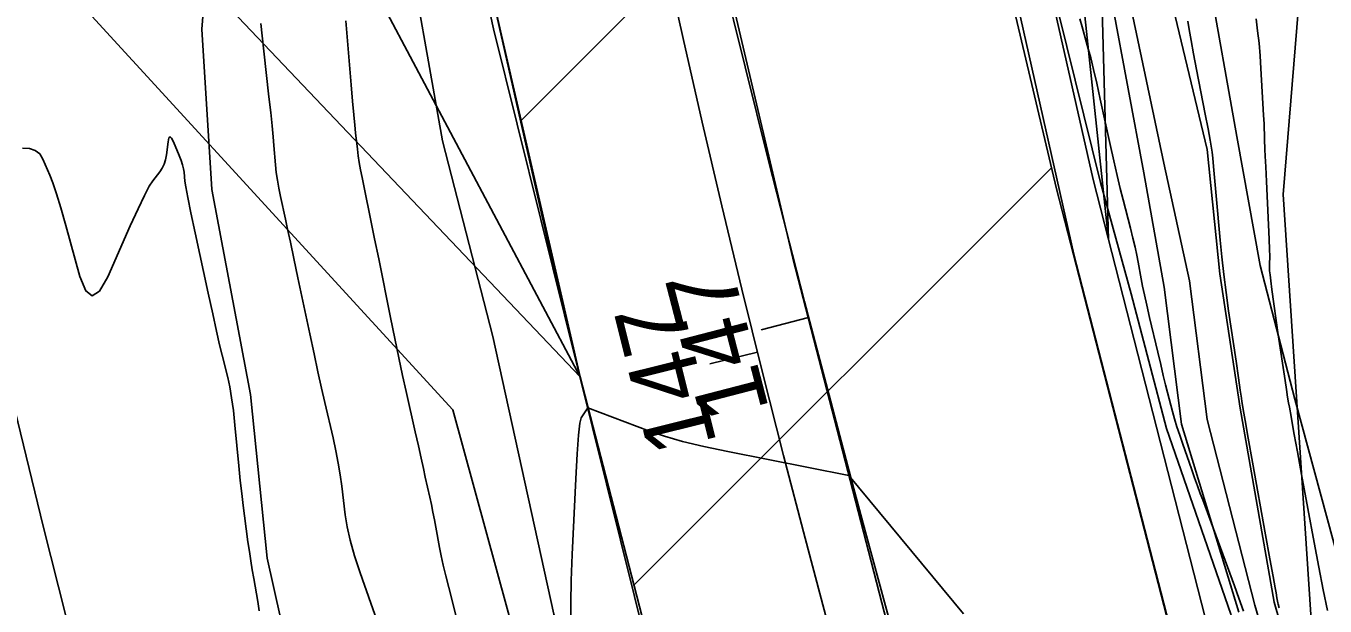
# Model space of a CAD drawing. Extents: x 2030588 to 2035216, y 462285 to 465007.
# Drawn here: x 2031244.3 to 2031297.3, y 464172.9 to 464196.5 of the extents above; entities that cross this region are included whole.
import ezdxf

# ---------------------------------------------------------------- set-up
doc = ezdxf.new("R2010")
doc.units = 0
for name, color, linetype in [('DR_X_Ditch', 7, 'Continuous'), ('DT_P_Pavement_Surface', 7, 'Continuous'), ('DT_P_Slope_Break_Line', 7, 'Continuous'), ('DT_X_Contour_Major', 7, 'Continuous'), ('DT_X_Contour_Minor', 7, 'Continuous'), ('GE_X_Alignment', 7, 'Continuous'), ('GE_X_Alignment_100_Stations', 7, 'Continuous'), ('MD_P_CONST_LIMITS', 7, 'Continuous'), ('PV_X_COP', 7, 'Continuous'), ('PV_X_EOP', 7, 'Continuous'), ('PV_X_Shoulder_Aggregate', 7, 'Continuous'), ('RW_X_CL', 7, 'Continuous'), ('RW_X_CL_100_Stations', 7, 'Continuous'), ('RW_X_Esmt_SH', 7, 'Continuous'), ('SV_X_Break_Lines', 7, 'Continuous'), ('SV_X_Toe_of_Slope', 7, 'Continuous'), ('SV_X_Top_of_Bank', 7, 'Continuous'), ('UT_X_Telecom', 7, 'Continuous')]:
    doc.layers.add(name, color=color, linetype=linetype)

msp = doc.modelspace()

# ---------------------------------------------------------------- linework, layer by layer
at = {"layer": 'DR_X_Ditch'}
msp.add_lwpolyline([(2031296.503, 464165.775), (2031294.416, 464172.894), (2031292.48, 464180.474), (2031291.756, 464186.133), (2031290.713, 464190.937), (2031289.295, 464197.655), (2031288.219, 464204.814), (2031286.616, 464211.861), (2031285.537, 464218.105), (2031285.112, 464221.471), (2031284.631, 464227.278), (2031284.497, 464231.677), (2031284.399, 464233.135), (2031284.113, 464233.687), (2031283.585, 464238.805), (2031282.994, 464242.68)], dxfattribs=at)
at = {"layer": 'DT_P_Pavement_Surface'}
for p, q in [((2031264.485, 464192.687), (2031281.619, 464209.821)), ((2031269.087, 464173.721), (2031286.12, 464190.754))]:
    msp.add_line(p, q, dxfattribs=at)
msp.add_lwpolyline([(2031278.406, 464242.26), (2031279.291, 464236.286), (2031282.911, 464211.855), (2031281.24, 464211.467), (2031281.443, 464210.564), (2031286.324, 464189.894), (2031290.945, 464171.988), (2031296.143, 464154.308), (2031300.701, 464140.215), (2031308.554, 464119.142), (2031298.227, 464114.968), (2031289.065, 464111.177), (2031284.681, 464122.798), (2031281.552, 464131.387), (2031280.87, 464133.486), (2031276.172, 464147.96), (2031272.883, 464159.049), (2031266.889, 464182.219), (2031261.238, 464206.822), (2031262.457, 464207.105), (2031257.072, 464231.726), (2031252.323, 464256.477)], dxfattribs=at)
at = {"layer": 'DT_P_Slope_Break_Line'}
for p, q in [((2031285.833, 464212.534), (2031288.455, 464187.817)), ((2031254.663, 464205.295), (2031266.889, 464182.219)), ((2031246.735, 464203.453), (2031266.889, 464182.219)), ((2031288.455, 464187.817), (2031288.162, 464198.563))]:
    msp.add_line(p, q, dxfattribs=at)
at = {"layer": 'DT_X_Contour_Major'}
for points in [[(2031294.471, 464196.829), (2031294.536, 464196.343), (2031294.592, 464195.843), (2031294.637, 464195.33), (2031294.672, 464194.803), (2031294.753, 464193.379), (2031294.78, 464192.904), (2031294.798, 464192.547), (2031294.809, 464192.308), (2031294.813, 464192.186), (2031294.811, 464192.019), (2031294.811, 464191.957), (2031294.812, 464191.897), (2031294.814, 464191.839), (2031294.817, 464191.783), (2031294.827, 464191.636), (2031294.834, 464191.505), (2031294.848, 464191.222), (2031294.869, 464190.786), (2031294.896, 464190.198), (2031294.98, 464188.429), (2031295.007, 464187.844), (2031295.024, 464187.415), (2031295.033, 464187.143), (2031295.033, 464187.028), (2031295.02, 464186.93), (2031295.016, 464186.894), (2031295.014, 464186.86), (2031295.014, 464186.828), (2031295.015, 464186.797), (2031295.021, 464186.718), (2031295.023, 464186.69), (2031295.024, 464186.667), (2031295.023, 464186.648), (2031295.022, 464186.634), (2031295.017, 464186.601), (2031295.022, 464186.541), (2031295.041, 464186.385), (2031295.074, 464186.134), (2031295.121, 464185.786), (2031295.371, 464183.941), (2031295.656, 464182.069), (2031295.713, 464181.7), (2031295.76, 464181.395), (2031295.799, 464181.155), (2031295.83, 464180.979), (2031295.898, 464180.596), (2031295.945, 464180.34), (2031296.032, 464179.86), (2031296.161, 464179.156), (2031296.331, 464178.227), (2031296.84, 464175.452), (2031297.028, 464174.45), (2031297.21, 464173.527), (2031297.386, 464172.681)], [(2031282.534, 464172.55), (2031277.856, 464178.194), (2031272.927, 464179.169), (2031271.935, 464179.378), (2031271.072, 464179.585), (2031270.337, 464179.792), (2031269.731, 464179.998), (2031267.202, 464180.959), (2031266.94, 464180.547), (2031266.884, 464180.326), (2031266.829, 464179.837), (2031266.774, 464179.081), (2031266.719, 464178.058), (2031266.574, 464174.974), (2031266.531, 464173.9), (2031266.51, 464172.988), (2031266.511, 464172.24)]]:
    msp.add_lwpolyline(points, dxfattribs=at)
at = {"layer": 'DT_X_Contour_Minor'}
for points in [[(2031257.332, 464196.746), (2031257.386, 464196.095), (2031257.552, 464194.142), (2031257.61, 464193.47), (2031257.659, 464192.918), (2031257.7, 464192.487), (2031257.732, 464192.176), (2031257.806, 464191.508), (2031257.839, 464191.248), (2031257.882, 464190.968), (2031257.935, 464190.669), (2031257.998, 464190.351), (2031258.18, 464189.477), (2031258.262, 464189.079), (2031258.372, 464188.538), (2031258.51, 464187.855), (2031258.676, 464187.031), (2031259.156, 464184.643), (2031259.331, 464183.783), (2031259.495, 464182.992), (2031259.649, 464182.271), (2031259.793, 464181.62), (2031260.163, 464179.976), (2031260.293, 464179.399), (2031260.405, 464178.899), (2031260.5, 464178.476), (2031260.577, 464178.13), (2031260.76, 464177.312), (2031260.827, 464177.004), (2031260.891, 464176.696), (2031260.951, 464176.387), (2031261.009, 464176.077), (2031261.159, 464175.25), (2031261.225, 464174.915), (2031261.309, 464174.532), (2031261.411, 464174.1), (2031261.532, 464173.619), (2031261.879, 464172.273)], [(2031293.954, 464172.661), (2031293.769, 464173.179), (2031293.586, 464173.684), (2031292.737, 464176.011), (2031292.294, 464177.195), (2031292.194, 464177.464), (2031292.085, 464177.764), (2031291.966, 464178.096), (2031291.837, 464178.458), (2031291.482, 464179.466), (2031291.356, 464179.833), (2031291.245, 464180.178), (2031291.147, 464180.501), (2031291.065, 464180.802), (2031290.863, 464181.576), (2031290.781, 464181.897), (2031290.687, 464182.278), (2031290.58, 464182.719), (2031290.462, 464183.221), (2031290.129, 464184.641), (2031290.014, 464185.139), (2031289.918, 464185.568), (2031289.842, 464185.928), (2031289.785, 464186.219), (2031289.661, 464186.904), (2031289.606, 464187.183), (2031289.535, 464187.507), (2031289.448, 464187.874), (2031289.344, 464188.287), (2031289.048, 464189.445), (2031288.932, 464189.912), (2031288.805, 464190.444), (2031288.668, 464191.041), (2031288.521, 464191.704), (2031288.116, 464193.559), (2031287.971, 464194.21), (2031287.842, 464194.769), (2031287.726, 464195.238), (2031287.626, 464195.616), (2031287.377, 464196.503), (2031287.283, 464196.832)], [(2031291.684, 464196.744), (2031291.743, 464196.392), (2031291.823, 464195.946), (2031291.924, 464195.405), (2031292.046, 464194.769), (2031292.4, 464192.947), (2031292.517, 464192.337), (2031292.603, 464191.875), (2031292.658, 464191.56), (2031292.682, 464191.392), (2031292.704, 464191.141), (2031292.719, 464190.975), (2031292.747, 464190.663), (2031292.788, 464190.205), (2031292.842, 464189.603), (2031293.005, 464187.802), (2031293.073, 464187.115), (2031293.153, 464186.404), (2031293.246, 464185.669), (2031293.353, 464184.911), (2031293.654, 464182.856), (2031293.753, 464182.175), (2031293.827, 464181.674), (2031293.874, 464181.351), (2031293.896, 464181.208), (2031293.917, 464181.066), (2031293.949, 464180.881), (2031294.029, 464180.431), (2031294.156, 464179.717), (2031294.331, 464178.738), (2031294.862, 464175.777), (2031295.038, 464174.795), (2031295.167, 464174.073), (2031295.251, 464173.608), (2031295.288, 464173.403), (2031295.325, 464173.199), (2031295.339, 464173.125), (2031295.353, 464173.057), (2031295.365, 464172.995), (2031295.378, 464172.939), (2031295.411, 464172.796)], [(2031253.872, 464196.65), (2031253.924, 464196.141), (2031253.992, 464195.508), (2031254.199, 464193.654), (2031254.269, 464193.009), (2031254.327, 464192.462), (2031254.371, 464192.015), (2031254.403, 464191.666), (2031254.468, 464190.869), (2031254.499, 464190.564), (2031254.543, 464190.247), (2031254.6, 464189.919), (2031254.669, 464189.579), (2031254.871, 464188.657), (2031254.96, 464188.248), (2031255.075, 464187.711), (2031255.216, 464187.047), (2031255.383, 464186.255), (2031255.863, 464183.974), (2031256.036, 464183.158), (2031256.196, 464182.42), (2031256.343, 464181.76), (2031256.476, 464181.179), (2031256.813, 464179.732), (2031256.93, 464179.202), (2031257.028, 464178.697), (2031257.108, 464178.217), (2031257.17, 464177.762), (2031257.309, 464176.58), (2031257.386, 464176.1), (2031257.515, 464175.547), (2031257.694, 464174.919), (2031257.925, 464174.218), (2031258.608, 464172.251)], [(2031244.144, 464191.56), (2031244.43, 464191.545), (2031244.664, 464191.464), (2031244.847, 464191.318), (2031244.978, 464191.106), (2031245.259, 464190.453), (2031245.378, 464190.141), (2031245.526, 464189.694), (2031245.701, 464189.114), (2031245.906, 464188.399), (2031246.488, 464186.312), (2031246.722, 464185.725), (2031246.989, 464185.528), (2031247.287, 464185.722), (2031247.618, 464186.306), (2031248.542, 464188.383), (2031248.859, 464189.082), (2031249.117, 464189.621), (2031249.316, 464190), (2031249.455, 464190.219), (2031249.747, 464190.592), (2031249.846, 464190.739), (2031249.924, 464190.902), (2031249.98, 464191.082), (2031250.016, 464191.277), (2031250.083, 464191.819), (2031250.116, 464191.971), (2031250.164, 464192.02), (2031250.227, 464191.966), (2031250.305, 464191.81), (2031250.535, 464191.255), (2031250.611, 464191.057), (2031250.67, 464190.876), (2031250.71, 464190.714), (2031250.733, 464190.57), (2031250.768, 464190.21), (2031250.804, 464189.977), (2031250.886, 464189.547), (2031251.015, 464188.921), (2031251.19, 464188.098), (2031251.719, 464185.64), (2031251.903, 464184.791), (2031252.059, 464184.086), (2031252.187, 464183.525), (2031252.287, 464183.107), (2031252.517, 464182.188), (2031252.6, 464181.808), (2031252.676, 464181.358), (2031252.746, 464180.839), (2031252.809, 464180.25), (2031252.968, 464178.586), (2031253.027, 464177.99), (2031253.085, 464177.452), (2031253.142, 464176.97), (2031253.197, 464176.544), (2031253.342, 464175.486), (2031253.398, 464175.094), (2031253.455, 464174.714), (2031253.514, 464174.345), (2031253.575, 464173.987), (2031253.739, 464173.048), (2031253.803, 464172.669)]]:
    msp.add_lwpolyline(points, dxfattribs=at)
at = {"layer": 'GE_X_Alignment'}
msp.add_ellipse((2032214.825, 464428.293), major_axis=(-647.882, 721.538), ratio=0.999987, start_param=0.998641, end_param=1.129131, dxfattribs=at)
at = {"layer": 'GE_X_Alignment_100_Stations'}
msp.add_line((2031276.218, 464184.64), (2031274.282, 464184.138), dxfattribs=at)
at = {"layer": 'MD_P_CONST_LIMITS'}
for points in [[(2031213.423, 464452.904), (2031204.569, 464426.156), (2031208.548, 464401.477), (2031212.527, 464376.798), (2031213.545, 464351.642), (2031212.78, 464331.262), (2031212.588, 464326.168), (2031200.6, 464313.585), (2031192.908, 464308.049), (2031189.455, 464298.429), (2031209.379, 464281.464), (2031213.118, 464275.067), (2031222.806, 464250.019), (2031227.688, 464225.695), (2031242.004, 464202.354), (2031261.7, 464180.872), (2031268.395, 464156.387), (2031275.973, 464131.824), (2031285.052, 464107.55), (2031291.211, 464093.27), (2031304.871, 464099.462)], [(2031304.871, 464099.462), (2031318.532, 464105.655), (2031311.904, 464118.546), (2031304.38, 464141.463), (2031297.225, 464164.67), (2031295.574, 464189.665), (2031297.675, 464215.284), (2031293.386, 464239.179), (2031288.691, 464262.969), (2031290.634, 464288.11), (2031294.17, 464303.872), (2031299.488, 464314.858)]]:
    msp.add_lwpolyline(points, dxfattribs=at)
at = {"layer": 'PV_X_COP'}
msp.add_lwpolyline([(2031345.188, 464029.832), (2031333.67, 464047.134), (2031321.647, 464066.894), (2031312.766, 464083.536), (2031304.429, 464100.871), (2031297.296, 464118.161), (2031290.962, 464134.785), (2031285.598, 464151.007), (2031280.258, 464168.89), (2031275.568, 464187.058), (2031270.599, 464208.238), (2031269.533, 464213.253), (2031265.078, 464235.308), (2031261.071, 464256.548), (2031257.559, 464275.914), (2031253.749, 464297.335), (2031250.237, 464316.556), (2031248.155, 464328.465)], dxfattribs=at)
at = {"layer": 'PV_X_EOP'}
for points in [[(2031295.06, 464096.69), (2031287.81, 464114.209), (2031281.552, 464131.387), (2031276.172, 464147.96), (2031272.883, 464159.049), (2031270.831, 464166.359), (2031266.261, 464184.745), (2031263.597, 464196.521), (2031261.604, 464205.334), (2031260.218, 464211.323), (2031255.622, 464233.278), (2031251.626, 464254.611), (2031248.06, 464273.969), (2031245.809, 464286.12), (2031244.042, 464295.612), (2031240.727, 464314.748), (2031237.529, 464334.128), (2031234.115, 464352.392), (2031233.443, 464356.077), (2031230.628, 464372.695), (2031227.228, 464392.461), (2031223.822, 464412.655), (2031220.382, 464434.076), (2031216.941, 464456.075)], [(2031353.162, 464035.71), (2031341.874, 464052.676), (2031332.716, 464067.744), (2031330.521, 464071.931), (2031322.023, 464088.196), (2031314.108, 464105.099), (2031307.351, 464122.147), (2031301.267, 464138.466), (2031296.143, 464154.308), (2031290.945, 464171.988), (2031286.324, 464189.894), (2031281.443, 464210.564), (2031280.322, 464215.544), (2031275.666, 464237.435), (2031271.643, 464258.648), (2031268.07, 464277.87), (2031264.482, 464299.113), (2031261, 464318.439), (2031259.92, 464324.373)]]:
    msp.add_lwpolyline(points, dxfattribs=at)
at = {"layer": 'PV_X_Shoulder_Aggregate'}
for points in [[(2031322.799, 464088.616), (2031315.02, 464105.504), (2031308.326, 464122.489), (2031302.318, 464138.797), (2031297.302, 464154.717), (2031292.39, 464172.399), (2031287.828, 464190.274), (2031283.175, 464210.826), (2031282.124, 464215.96), (2031277.635, 464237.84), (2031273.355, 464258.914)], [(2031294.666, 464096.538), (2031287.417, 464114.11), (2031281.132, 464131.175), (2031275.919, 464147.847), (2031272.883, 464159.049), (2031270.831, 464166.359), (2031266.261, 464184.745), (2031263.356, 464196.421), (2031261.413, 464205.303), (2031259.964, 464211.309), (2031255.511, 464233.314), (2031251.402, 464254.597)]]:
    msp.add_lwpolyline(points, dxfattribs=at)
at = {"layer": 'RW_X_CL'}
msp.add_ellipse((2031830.081, 464321.523), major_axis=(-382.715, 426.319), ratio=0.999987, start_param=0.998751, end_param=1.776295, dxfattribs=at)
at = {"layer": 'RW_X_CL_100_Stations'}
msp.add_line((2031274.125, 464183.228), (2031272.184, 464182.746), dxfattribs=at)
at = {"layer": 'RW_X_Esmt_SH'}
msp.add_lwpolyline([(2031270.23, 464097.808), (2031267.91, 464103.703), (2031265.652, 464109.622), (2031263.457, 464115.564), (2031261.324, 464121.529), (2031259.254, 464127.516), (2031257.247, 464133.525), (2031255.303, 464139.554), (2031253.423, 464145.603), (2031251.606, 464151.672), (2031249.853, 464157.76), (2031248.165, 464163.865), (2031246.54, 464169.988), (2031244.98, 464176.128), (2031243.485, 464182.284), (2031242.054, 464188.455), (2031240.688, 464194.641), (2031239.387, 464200.841), (2031238.152, 464207.054), (2031236.982, 464213.28), (2031235.877, 464219.518), (2031234.838, 464225.767)], dxfattribs=at)
at = {"layer": 'SV_X_Break_Lines'}
for points in [[(2031279.184, 464230.728), (2031281.431, 464220.57), (2031282.015, 464217.367), (2031283.335, 464211.146), (2031284.794, 464203.774), (2031286.418, 464197.084), (2031288.119, 464190.155), (2031289.378, 464185.603), (2031290.824, 464180.11), (2031293.444, 464172.527), (2031295.235, 464165.396), (2031296.873, 464159.344), (2031297.803, 464155.004), (2031300.31, 464146.294), (2031302.745, 464138.963), (2031304.623, 464134.105), (2031306.989, 464127.43), (2031308.732, 464122.376), (2031310.328, 464118.347), (2031313.222, 464111.465), (2031315.576, 464105.532), (2031318.909, 464097.312)], [(2031288.534, 464093.79), (2031283.056, 464105), (2031281.645, 464111.552), (2031278.999, 464120.783), (2031277.267, 464129.637), (2031275.319, 464136.973), (2031272.566, 464142.866), (2031272.832, 464147.121), (2031269.651, 464157.069), (2031267.678, 464165.709), (2031265.817, 464172.533), (2031263.335, 464183.872), (2031261.278, 464191.859), (2031260.222, 464197.853), (2031258.128, 464205.793)]]:
    msp.add_lwpolyline(points, dxfattribs=at)
at = {"layer": 'SV_X_Toe_of_Slope'}
for points in [[(2031293.774, 464172.608), (2031291.435, 464180.285), (2031290.729, 464185.879), (2031289.893, 464190.553), (2031288.611, 464197.405), (2031287.426, 464204.588), (2031285.872, 464211.617), (2031284.765, 464217.99), (2031284.409, 464221.464), (2031283.902, 464227.062), (2031283.957, 464231.729), (2031283.779, 464233.107), (2031283.593, 464233.552), (2031282.916, 464238.677), (2031282.163, 464242.433)], [(2031247.281, 464239.517), (2031247.661, 464235.04), (2031247.677, 464232.194), (2031247.78, 464227.191), (2031247.966, 464222.776), (2031248.617, 464218.966), (2031249.455, 464213.074), (2031250.036, 464209.9), (2031250.799, 464204.241), (2031251.778, 464200.335), (2031251.466, 464196.416), (2031251.867, 464189.872), (2031253.447, 464181.497), (2031254.127, 464174.814), (2031255.471, 464168.787), (2031257.652, 464162.605), (2031259.455, 464159.072), (2031260.695, 464153.985), (2031260.837, 464143.657), (2031260.556, 464136.172), (2031261.225, 464131.193), (2031263.169, 464126.092)], [(2031285.316, 464233.158), (2031286.09, 464232.97), (2031286.896, 464232.063), (2031287.199, 464229.173), (2031287.082, 464227.563), (2031287.628, 464222.04), (2031288.032, 464218.598), (2031288.594, 464212.108), (2031289.523, 464205.203), (2031290.93, 464197.975), (2031292.472, 464191.495), (2031292.994, 464186.424), (2031293.827, 464180.942), (2031295.205, 464173.02), (2031297.242, 464165.988)]]:
    msp.add_lwpolyline(points, dxfattribs=at)
at = {"layer": 'SV_X_Top_of_Bank'}
msp.add_lwpolyline([(2031285.389, 464233.908), (2031286.523, 464233.387), (2031287.459, 464232.202), (2031287.896, 464230.453), (2031287.594, 464229.321), (2031287.807, 464227.816), (2031288.573, 464222.336), (2031288.732, 464218.735), (2031289.258, 464212.201), (2031290.775, 464205.638), (2031292.525, 464198.542), (2031293.682, 464192.026), (2031294.638, 464186.768), (2031296.052, 464181.312), (2031298.162, 464173.534), (2031299.494, 464166.843)], dxfattribs=at)
at = {"layer": 'UT_X_Telecom'}
msp.add_lwpolyline([(2031361.709, 464028.542), (2031356.786, 464035.327), (2031347.681, 464048.933), (2031339.944, 464060.397), (2031329.726, 464073.814), (2031321.673, 464087.15), (2031313.33, 464106.65), (2031305.91, 464124.388), (2031298.718, 464143.455), (2031292.601, 464165.642), (2031287.039, 464187.229), (2031282.348, 464208.081), (2031277.602, 464228.834), (2031275.079, 464242.094), (2031273.133, 464253.288), (2031272.708, 464257.728), (2031274.398, 464259.6), (2031278.694, 464259.868), (2031283.757, 464259.769), (2031285.497, 464261.094)], dxfattribs=at)

# ---------------------------------------------------------------- texts
at = {"layer": 'GE_X_Alignment_100_Stations'}
msp.add_text('147', height=2.7997, rotation=104.5528, dxfattribs=at).set_placement((2031274.613, 464180.874))
at = {"layer": 'RW_X_CL_100_Stations'}
msp.add_text('147', height=2.7997, rotation=103.9695, dxfattribs=at).set_placement((2031272.482, 464179.478))

doc.saveas('drawing.dxf')
